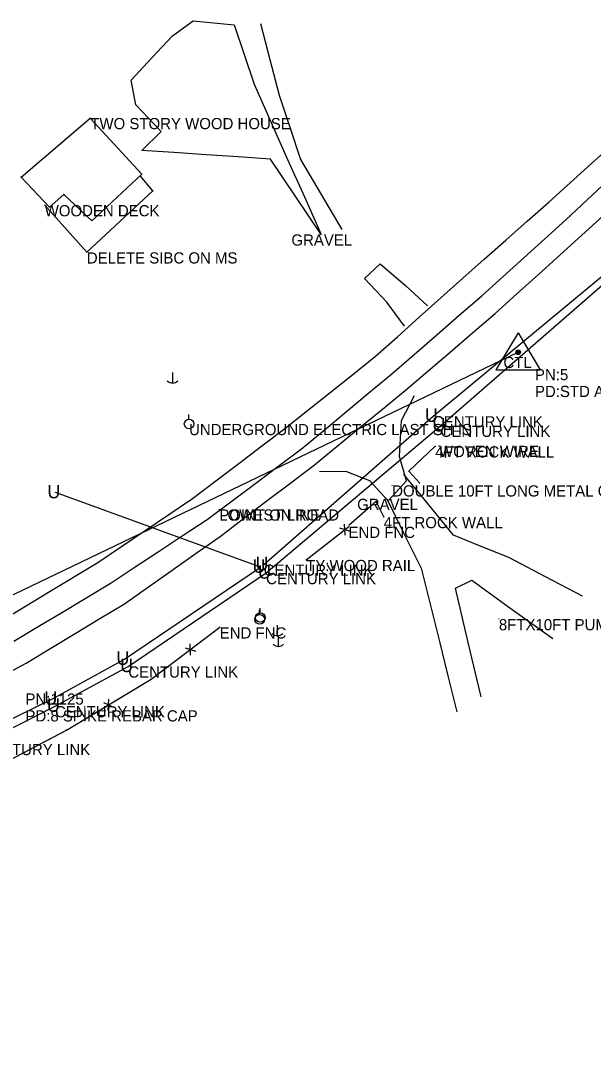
# Model space of a CAD drawing. Extents: x 1568433 to 1572450, y 731863 to 733450.
# Drawn here: x 1571760.5 to 1572016, y 732336.5 to 732803.2 of the extents above; entities that cross this region are included whole.
import ezdxf

# ---------------------------------------------------------------- set-up
doc = ezdxf.new("R2010")
doc.units = 0
for name, color, linetype in [('Default', 7, 'Continuous'), ('S_BASELINE', 7, 'Continuous'), ('S_BUILDING', 7, 'Continuous'), ('S_BUILDING_ANNOT', 7, 'Continuous'), ('S_DRIVEWAY', 7, 'Continuous'), ('S_DRIVEWAY_ANNOT', 7, 'Continuous'), ('S_EDGE_PAVEMENT', 7, 'Continuous'), ('S_ELECTRIC_UTILITIES_ANNOT', 7, 'Continuous'), ('S_FENCE', 7, 'Continuous'), ('S_FENCE_ANNOT', 7, 'Continuous'), ('S_GATE_ANNOT', 7, 'Continuous'), ('S_MISC_STRUCTURES', 7, 'Continuous'), ('S_MISC_STRUCTURES_ANNOT', 7, 'Continuous'), ('S_MSC_PT_SYM', 7, 'Continuous'), ('S_PAVEMENT_CROWN', 7, 'Continuous'), ('S_PRIMARY_CTL', 7, 'Continuous'), ('S_PRIMARY_CTL_ANNOT', 7, 'Continuous'), ('S_SECONDARY_CTL_ANNOT', 7, 'Continuous'), ('S_STR_PT_SYM', 7, 'Continuous'), ('S_SURVEY_TEXT_ANNOT', 7, 'Continuous'), ('S_UNDERGROUND_CABLE', 7, 'Continuous'), ('S_UNDERGROUND_CABLE_ANNOT', 7, 'Continuous'), ('S_UTILITY_POLE', 7, 'Continuous'), ('S_UTILITY_POLE_ANNOT', 7, 'Continuous'), ('S_UTL_PT_SYM', 7, 'Continuous'), ('S_WALL', 7, 'Continuous'), ('S_WALL_ANNOT', 7, 'Continuous')]:
    doc.layers.add(name, color=color, linetype=linetype)

msp = doc.modelspace()

# ---------------------------------------------------------------- linework, layer by layer
at = {"layer": 'S_BASELINE'}
msp.add_line((1571317.07, 732336.49), (1571982.53, 732655.39), dxfattribs=at)
at = {"layer": 'S_BUILDING'}
for p, q in [((1571760.57, 732733.52), (1571791.49, 732759.87)), ((1571791.49, 732759.87), (1571814.53, 732734.83)), ((1571814.53, 732734.83), (1571792.15, 732714.04)), ((1571773.25, 732720.02), (1571760.57, 732733.52)), ((1571779.62, 732725.79), (1571773.25, 732720.02)), ((1571792.15, 732714.04), (1571779.62, 732725.79))]:
    msp.add_line(p, q, dxfattribs=at)
at = {"layer": 'S_DRIVEWAY'}
msp.add_lwpolyline([(1571894.55, 732707.95), (1571883.22, 732724.74), (1571871.9, 732741.54), (1571857.54, 732742.51), (1571843.18, 732743.49), (1571828.82, 732744.46), (1571814.47, 732745.44), (1571823.08, 732753.84), (1571811.81, 732765.73), (1571809.66, 732776.81), (1571818.89, 732786.69), (1571828.12, 732796.57), (1571837.35, 732803.18), (1571855.77, 732801.38), (1571860.2, 732788.14), (1571864.63, 732774.9), (1571872.11, 732758.16), (1571879.59, 732741.42), (1571887.07, 732724.69)], close=True, dxfattribs=at)
for points in [[(1571867.46, 732802), (1571871.67, 732786.04), (1571875.89, 732770.08), (1571880.59, 732755.73), (1571885.29, 732741.37), (1571894.57, 732725.77), (1571903.84, 732710.17)], [(1571931.75, 732666.96), (1571923.96, 732677.68), (1571913.97, 732688.23), (1571920.85, 732694.75), (1571932.28, 732685.2), (1571942.09, 732676.01)], [(1571893.77, 732602.31), (1571905.84, 732602.22), (1571916.09, 732598.23), (1571924.45, 732589.16), (1571932.71, 732598.02), (1571929.56, 732608.83), (1571930.49, 732624.94), (1571936.23, 732636.07)], [(1572011.22, 732546.55), (1571994.81, 732555.15), (1571978.4, 732563.76), (1571966.06, 732568.75), (1571953.71, 732573.73), (1571942.59, 732587.3), (1571931.46, 732600.86)], [(1571923.91, 732589.99), (1571931.55, 732574.5), (1571939.19, 732559.02), (1571943.19, 732543.01), (1571947.19, 732527), (1571951.19, 732511), (1571955.19, 732494.99)], [(1571966, 732501.73), (1571960.26, 732525.94), (1571954.51, 732550.16), (1571961.78, 732553.66), (1571979.88, 732540.67), (1571997.98, 732527.67)]]:
    msp.add_lwpolyline(points, dxfattribs=at)
at = {"layer": 'S_EDGE_PAVEMENT'}
for points in [[(1571752.3, 732535.9), (1571773.57, 732548.77), (1571794.83, 732561.64), (1571805.41, 732568.77), (1571815.99, 732575.9), (1571826.57, 732583.03), (1571837.15, 732590.16), (1571847.47, 732597.97), (1571857.78, 732605.78), (1571868.1, 732613.59), (1571878.41, 732621.4), (1571888.53, 732629.44), (1571898.65, 732637.48), (1571908.77, 732645.52), (1571918.88, 732653.56), (1571928.61, 732662.28), (1571938.33, 732670.99), (1571948.05, 732679.71), (1571957.77, 732688.43), (1571967.38, 732696.91), (1571976.99, 732705.39), (1571986.6, 732713.87), (1571996.2, 732722.35), (1572005.78, 732730.97), (1572015.35, 732739.59), (1572024.93, 732748.21)], [(1571751.48, 732510.6), (1571762.8, 732516.69), (1571773.8, 732523.31), (1571784.8, 732529.92), (1571795.8, 732536.53), (1571806.8, 732543.15), (1571817.45, 732550.67), (1571828.1, 732558.19), (1571838.75, 732565.71), (1571849.4, 732573.22), (1571859.95, 732581.21), (1571870.49, 732589.19), (1571881.03, 732597.17), (1571891.58, 732605.15), (1571901.72, 732613.44), (1571911.86, 732621.74), (1571922, 732630.03), (1571932.15, 732638.32), (1571942.16, 732646.89), (1571952.17, 732655.47), (1571962.19, 732664.05), (1571972.2, 732672.62), (1571981.88, 732681.37), (1571991.57, 732690.11), (1572001.25, 732698.86), (1572010.94, 732707.6), (1572020.43, 732716.21)]]:
    msp.add_lwpolyline(points, dxfattribs=at)
at = {"layer": 'S_FENCE'}
for p, q in [((1571887.9, 732562.73), (1571906.78, 732577.53)), ((1571902.75, 732576.98), (1571907.52, 732575.52)), ((1571902.75, 732576.98), (1571907.52, 732575.52)), ((1571905.28, 732573.75), (1571905, 732578.74)), ((1571905.28, 732573.75), (1571905, 732578.74)), ((1571818.67, 732509.54), (1571849.28, 732532.67)), ((1571836.27, 732520.27), (1571836.08, 732525.26)), ((1571836.27, 732520.27), (1571836.08, 732525.26)), ((1571833.8, 732523.54), (1571838.55, 732521.99)), ((1571833.8, 732523.54), (1571838.55, 732521.99)), ((1571780.79, 732486.82), (1571818.67, 732509.54)), ((1571797.34, 732499.14), (1571801.9, 732497.09)), ((1571797.34, 732499.14), (1571801.9, 732497.09)), ((1571799.44, 732495.62), (1571799.79, 732500.61)), ((1571799.44, 732495.62), (1571799.79, 732500.61)), ((1571738.13, 732464.28), (1571780.79, 732486.82))]:
    msp.add_line(p, q, dxfattribs=at)
for points in [[(1571906.7, 732577.48), (1571906.78, 732577.53)], [(1571906.7, 732577.48), (1571906.78, 732577.53)], [(1571887.9, 732562.73), (1571903.57, 732575.02)], [(1571887.9, 732562.73), (1571903.57, 732575.02)], [(1571837.77, 732523.97), (1571849.28, 732532.67)], [(1571837.77, 732523.97), (1571849.28, 732532.67)], [(1571818.67, 732509.54), (1571834.58, 732521.56)], [(1571818.67, 732509.54), (1571834.58, 732521.56)], [(1571801.33, 732499.14), (1571818.67, 732509.54)], [(1571801.33, 732499.14), (1571818.67, 732509.54)], [(1571780.79, 732486.82), (1571797.91, 732497.09)], [(1571780.79, 732486.82), (1571797.91, 732497.09)], [(1571759.3, 732475.47), (1571780.79, 732486.82)], [(1571759.3, 732475.47), (1571780.79, 732486.82)]]:
    msp.add_lwpolyline(points, dxfattribs=at)
at = {"layer": 'S_MISC_STRUCTURES'}
for p, q in [((1571819.47, 732727.41), (1571813.91, 732733.92)), ((1571789.94, 732699.96), (1571819.47, 732727.41)), ((1571771.11, 732721.01), (1571789.94, 732699.96))]:
    msp.add_line(p, q, dxfattribs=at)
at = {"layer": 'S_MSC_PT_SYM'}
for points in [[(1571813.91, 732733.92), (1571813.91, 732733.97), (1571813.91, 732733.92), (1571813.86, 732733.92), (1571813.91, 732733.92), (1571813.91, 732733.87), (1571813.91, 732733.92), (1571813.96, 732733.92)], [(1571819.47, 732727.41), (1571819.47, 732727.46), (1571819.47, 732727.41), (1571819.42, 732727.41), (1571819.47, 732727.41), (1571819.47, 732727.36), (1571819.47, 732727.41), (1571819.52, 732727.41)], [(1571771.11, 732721.01), (1571771.11, 732721.06), (1571771.11, 732721.01), (1571771.06, 732721.01), (1571771.11, 732721.01), (1571771.11, 732720.96), (1571771.11, 732721.01), (1571771.16, 732721.01)], [(1571789.94, 732699.96), (1571789.94, 732700.01), (1571789.94, 732699.96), (1571789.89, 732699.96), (1571789.94, 732699.96), (1571789.94, 732699.91), (1571789.94, 732699.96), (1571789.99, 732699.96)], [(1571945.51, 732613.42), (1571945.51, 732613.47), (1571945.51, 732613.42), (1571945.46, 732613.42), (1571945.51, 732613.42), (1571945.51, 732613.37), (1571945.51, 732613.42), (1571945.56, 732613.42)], [(1571947.22, 732613.64), (1571947.22, 732613.69), (1571947.22, 732613.64), (1571947.17, 732613.64), (1571947.22, 732613.64), (1571947.22, 732613.59), (1571947.22, 732613.64), (1571947.27, 732613.64)], [(1571933.71, 732602.29), (1571933.71, 732602.34), (1571933.71, 732602.29), (1571933.66, 732602.29), (1571933.71, 732602.29), (1571933.71, 732602.24), (1571933.71, 732602.29), (1571933.76, 732602.29)], [(1571926.28, 732596.02), (1571926.28, 732596.07), (1571926.28, 732596.02), (1571926.23, 732596.02), (1571926.28, 732596.02), (1571926.28, 732595.97), (1571926.28, 732596.02), (1571926.33, 732596.02)], [(1571938.56, 732596.98), (1571938.56, 732597.03), (1571938.56, 732596.98), (1571938.51, 732596.98), (1571938.56, 732596.98), (1571938.56, 732596.93), (1571938.56, 732596.98), (1571938.61, 732596.98)], [(1571775.96, 732592.75), (1571775.96, 732592.8), (1571775.96, 732592.75), (1571775.91, 732592.75), (1571775.96, 732592.75), (1571775.96, 732592.7), (1571775.96, 732592.75), (1571776.01, 732592.75)], [(1571849.08, 732585.26), (1571849.08, 732585.31), (1571849.08, 732585.26), (1571849.03, 732585.26), (1571849.08, 732585.26), (1571849.08, 732585.21), (1571849.08, 732585.26), (1571849.13, 732585.26)], [(1571919.16, 732588.86), (1571919.16, 732588.91), (1571919.16, 732588.86), (1571919.11, 732588.86), (1571919.16, 732588.86), (1571919.16, 732588.81), (1571919.16, 732588.86), (1571919.21, 732588.86)], [(1571849.45, 732584.94), (1571849.45, 732584.99), (1571849.45, 732584.94), (1571849.4, 732584.94), (1571849.45, 732584.94), (1571849.45, 732584.89), (1571849.45, 732584.94), (1571849.5, 732584.94)], [(1571922.49, 732581.89), (1571922.49, 732581.94), (1571922.49, 732581.89), (1571922.44, 732581.89), (1571922.49, 732581.89), (1571922.49, 732581.84), (1571922.49, 732581.89), (1571922.54, 732581.89)], [(1571906.78, 732577.53), (1571906.78, 732577.58), (1571906.78, 732577.53), (1571906.73, 732577.53), (1571906.78, 732577.53), (1571906.78, 732577.48), (1571906.78, 732577.53), (1571906.83, 732577.53)], [(1571906.98, 732578.08), (1571906.98, 732578.13), (1571906.98, 732578.08), (1571906.93, 732578.08), (1571906.98, 732578.08), (1571906.98, 732578.03), (1571906.98, 732578.08), (1571907.03, 732578.08)], [(1571887.9, 732562.73), (1571887.9, 732562.78), (1571887.9, 732562.73), (1571887.85, 732562.73), (1571887.9, 732562.73), (1571887.9, 732562.68), (1571887.9, 732562.73), (1571887.95, 732562.73)], [(1571973.92, 732536.35), (1571973.92, 732536.4), (1571973.92, 732536.35), (1571973.87, 732536.35), (1571973.92, 732536.35), (1571973.92, 732536.3), (1571973.92, 732536.35), (1571973.97, 732536.35)], [(1571849.28, 732532.67), (1571849.28, 732532.72), (1571849.28, 732532.67), (1571849.23, 732532.67), (1571849.28, 732532.67), (1571849.28, 732532.62), (1571849.28, 732532.67), (1571849.33, 732532.67)], [(1571818.67, 732509.54), (1571818.67, 732509.59), (1571818.67, 732509.54), (1571818.62, 732509.54), (1571818.67, 732509.54), (1571818.67, 732509.49), (1571818.67, 732509.54), (1571818.72, 732509.54)], [(1571780.79, 732486.82), (1571780.79, 732486.87), (1571780.79, 732486.82), (1571780.74, 732486.82), (1571780.79, 732486.82), (1571780.79, 732486.77), (1571780.79, 732486.82), (1571780.84, 732486.82)]]:
    msp.add_lwpolyline(points, dxfattribs=at)
at = {"layer": 'S_PAVEMENT_CROWN'}
msp.add_lwpolyline([(1571757.34, 732526.42), (1571768.19, 732532.96), (1571779.04, 732539.5), (1571789.9, 732546.04), (1571800.75, 732552.58), (1571811.49, 732559.63), (1571822.22, 732566.69), (1571832.96, 732573.74), (1571843.7, 732580.8), (1571854.22, 732588.68), (1571864.74, 732596.57), (1571875.26, 732604.46), (1571885.78, 732612.34), (1571895.85, 732620.68), (1571905.93, 732629.01), (1571916.01, 732637.35), (1571926.08, 732645.68), (1571936.12, 732654.41), (1571946.16, 732663.14), (1571956.21, 732671.86), (1571966.25, 732680.59), (1571975.65, 732689.06), (1571985.05, 732697.54), (1571994.45, 732706.02), (1572003.86, 732714.49), (1572013.22, 732723.24), (1572022.58, 732731.99)], dxfattribs=at)
at = {"layer": 'S_PRIMARY_CTL'}
for p, q in [((1571982.53, 732664.09), (1571972.5, 732647.58)), ((1571982.53, 732664.09), (1571972.5, 732647.58)), ((1571982.53, 732664.09), (1571992.35, 732647.58)), ((1571982.53, 732664.09), (1571992.35, 732647.58)), ((1571972.5, 732647.58), (1571992.35, 732647.58)), ((1571972.5, 732647.58), (1571992.35, 732647.58))]:
    msp.add_line(p, q, dxfattribs=at)
for radius in [1.04, 1.04, 0.609, 0.609, 0.344, 0.344]:
    msp.add_circle((1571982.53, 732655.39), radius, dxfattribs=at)
at = {"layer": 'S_STR_PT_SYM'}
for points in [[(1571791.49, 732759.87), (1571791.49, 732759.92), (1571791.49, 732759.87), (1571791.44, 732759.87), (1571791.49, 732759.87), (1571791.49, 732759.82), (1571791.49, 732759.87), (1571791.54, 732759.87)], [(1571814.53, 732734.83), (1571814.53, 732734.88), (1571814.53, 732734.83), (1571814.48, 732734.83), (1571814.53, 732734.83), (1571814.53, 732734.77), (1571814.53, 732734.83), (1571814.58, 732734.83)], [(1571760.57, 732733.52), (1571760.57, 732733.57), (1571760.57, 732733.52), (1571760.52, 732733.52), (1571760.57, 732733.52), (1571760.57, 732733.47), (1571760.57, 732733.52), (1571760.62, 732733.52)], [(1571779.62, 732725.79), (1571779.62, 732725.84), (1571779.62, 732725.79), (1571779.57, 732725.79), (1571779.62, 732725.79), (1571779.62, 732725.74), (1571779.62, 732725.79), (1571779.67, 732725.79)], [(1571773.25, 732720.02), (1571773.25, 732720.07), (1571773.25, 732720.02), (1571773.2, 732720.02), (1571773.25, 732720.02), (1571773.25, 732719.97), (1571773.25, 732720.02), (1571773.3, 732720.02)], [(1571792.15, 732714.04), (1571792.15, 732714.09), (1571792.15, 732714.04), (1571792.1, 732714.04), (1571792.15, 732714.04), (1571792.15, 732713.99), (1571792.15, 732714.04), (1571792.2, 732714.04)]]:
    msp.add_lwpolyline(points, dxfattribs=at)
at = {"layer": 'S_UNDERGROUND_CABLE'}
for p, q in [((1571944.52, 732626.86), (1572023.78, 732692.45)), ((1571947.87, 732622.6), (1572025.85, 732690.34)), ((1571868.91, 732560.67), (1571944.52, 732626.86)), ((1571870.01, 732556.9), (1571947.87, 732622.6)), ((1571867.55, 732559.56), (1571775.96, 732592.75)), ((1571806.77, 732518.45), (1571867.55, 732559.56)), ((1571808.46, 732515.24), (1571870.01, 732556.9)), ((1571774.59, 732500.7), (1571806.77, 732518.45)), ((1571775.74, 732497.5), (1571808.46, 732515.24)), ((1571740.21, 732484.06), (1571774.59, 732500.7)), ((1571742.41, 732480.65), (1571775.74, 732497.5))]:
    msp.add_line(p, q, dxfattribs=at)
at = {"layer": 'S_UTILITY_POLE'}
for p, q in [((1571828.14, 732646.39), (1571828.14, 732641.67)), ((1571835.47, 732625.53), (1571835.47, 732627.64)), ((1571867, 732538.36), (1571867, 732540.47)), ((1571867.3, 732539.17), (1571867.3, 732541.28)), ((1571874.99, 732533.69), (1571874.99, 732528.97)), ((1571875.4, 732528.86), (1571875.4, 732524.13))]:
    msp.add_line(p, q, dxfattribs=at)
for centre in [(1571835.59, 732623.39), (1571867.42, 732537.03), (1571867.12, 732536.22)]:
    msp.add_circle(centre, 2.13, dxfattribs=at)
for centre in [(1571828.21, 732645.09), (1571875.05, 732532.39), (1571875.46, 732527.56)]:
    msp.add_arc(centre, 3.41, 226.3972, 313.6028, dxfattribs=at)
at = {"layer": 'S_UTL_PT_SYM'}
for points in [[(1571849.08, 732585.26), (1571849.08, 732585.31), (1571849.08, 732585.26), (1571849.03, 732585.26), (1571849.08, 732585.26), (1571849.08, 732585.21), (1571849.08, 732585.26), (1571849.13, 732585.26)], [(1571849.45, 732584.94), (1571849.45, 732584.99), (1571849.45, 732584.94), (1571849.4, 732584.94), (1571849.45, 732584.94), (1571849.45, 732584.89), (1571849.45, 732584.94), (1571849.5, 732584.94)]]:
    msp.add_lwpolyline(points, dxfattribs=at)
at = {"layer": 'S_WALL'}
for p, q in [((1571945.51, 732613.42), (1571933.71, 732602.29)), ((1571933.71, 732602.29), (1571938.56, 732596.98)), ((1571919.16, 732588.86), (1571906.98, 732578.08)), ((1571922.49, 732581.89), (1571919.16, 732588.86))]:
    msp.add_line(p, q, dxfattribs=at)
for points in [[(1571945.51, 732613.42), (1571933.71, 732602.29), (1571938.56, 732596.98)], [(1571922.49, 732581.89), (1571919.16, 732588.86), (1571906.98, 732578.08)]]:
    msp.add_lwpolyline(points, dxfattribs=at)

# ---------------------------------------------------------------- texts
at = {"layer": 'Default'}
for p in [(1571940.89, 732624.31), (1571944.24, 732620.05), (1571772.33, 732590.21), (1571863.92, 732557.02), (1571865.28, 732558.12), (1571866.38, 732554.36), (1571803.14, 732515.9), (1571804.83, 732512.69), (1571770.96, 732498.16), (1571772.11, 732494.96)]:
    msp.add_text('U', height=6, dxfattribs=at).set_placement(p)
at = {"layer": 'S_BUILDING_ANNOT'}
msp.add_text('TWO STORY WOOD HOUSE', height=5, dxfattribs=at).set_placement((1571791.49, 732754.87))
at = {"layer": 'S_DRIVEWAY_ANNOT'}
for p in [(1571881.28, 732702.95), (1571910.64, 732584.99)]:
    msp.add_text('GRAVEL', height=5, dxfattribs=at).set_placement(p)
at = {"layer": 'S_ELECTRIC_UTILITIES_ANNOT'}
msp.add_text('LOWEST LINE', height=5, dxfattribs=at).set_placement((1571849.08, 732580.26))
at = {"layer": 'S_FENCE_ANNOT'}
for s, p in [('WOVEN WIRE', (1571947.22, 732608.64)), ('END FNC', (1571906.78, 732572.53)), ('TY:WOOD RAIL', (1571887.9, 732557.73)), ('END FNC', (1571849.28, 732527.67))]:
    msp.add_text(s, height=5, dxfattribs=at).set_placement(p)
at = {"layer": 'S_GATE_ANNOT'}
msp.add_text('DOUBLE 10FT LONG METAL GT', height=5, dxfattribs=at).set_placement((1571926.28, 732591.02))
at = {"layer": 'S_MISC_STRUCTURES_ANNOT'}
for s, p in [('WOODEN DECK', (1571771.11, 732716.01)), ('DELETE SIBC ON MS', (1571789.94, 732694.96))]:
    msp.add_text(s, height=5, dxfattribs=at).set_placement(p)
at = {"layer": 'S_PRIMARY_CTL'}
msp.add_text('CTL', height=5, rotation=360, dxfattribs=at).set_placement((1571975.94, 732648.32))
msp.add_text('CTL', height=5, dxfattribs=at).set_placement((1571975.94, 732648.32))
at = {"layer": 'S_PRIMARY_CTL_ANNOT'}
for s, p in [('PN:5', (1571990.03, 732642.89)), ('PD:STD ARDOT CAP STAMPED PN:5', (1571990.03, 732635.39))]:
    msp.add_text(s, height=5, dxfattribs=at).set_placement(p)
at = {"layer": 'S_SECONDARY_CTL_ANNOT'}
for s, p in [('PN:1125', (1571762.52, 732498.17)), ('PD:8 SPIKE REBAR CAP', (1571762.52, 732490.67))]:
    msp.add_text(s, height=5, dxfattribs=at).set_placement(p)
at = {"layer": 'S_SURVEY_TEXT_ANNOT'}
for s, p in [('POINT ON ROAD', (1571849.08, 732580.26)), ('8FTX10FT PUMP SHED', (1571973.92, 732531.35))]:
    msp.add_text(s, height=5, dxfattribs=at).set_placement(p)
at = {"layer": 'S_UNDERGROUND_CABLE_ANNOT'}
for p in [(1571944.52, 732621.86), (1571947.87, 732617.6), (1571868.91, 732555.67), (1571870.01, 732551.9), (1571808.46, 732510.24), (1571775.74, 732492.5), (1571742.41, 732475.65)]:
    msp.add_text('CENTURY LINK', height=5, dxfattribs=at).set_placement(p)
at = {"layer": 'S_UTILITY_POLE_ANNOT'}
msp.add_text('UNDERGROUND ELECTRIC LAST SH IS', height=5, dxfattribs=at).set_placement((1571835.59, 732618.39))
at = {"layer": 'S_WALL_ANNOT'}
for p in [(1571945.51, 732608.42), (1571922.49, 732576.89)]:
    msp.add_text('4FT ROCK WALL', height=5, dxfattribs=at).set_placement(p)

doc.saveas('drawing.dxf')
